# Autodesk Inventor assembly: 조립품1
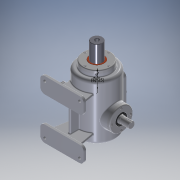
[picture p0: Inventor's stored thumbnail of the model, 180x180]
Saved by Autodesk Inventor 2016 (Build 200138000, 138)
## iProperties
Created: 2018-11
Part Number: 조립품1
Material: 일반
Document SubType Name: Assembly
Designer: user
Mass: 8191.33 g
Surface Area: 4241.85 cm^2
Volume: 1855.51 cm^3
Density: 4.41461 g/cm^3
Author: user
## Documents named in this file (15)
- C:\Users\user\Desktop\381121V1010\조립품1.iam
- C:\Users\user\Desktop\381121V1010\상부커버.ipt
- C:\Users\user\Desktop\381121V1010\슬라이드 커버.ipt
- C:\Users\user\Desktop\381121V1010\슬라이드.ipt
- C:\Users\user\Desktop\381121V1010\오일실.ipt
- 오일실.ipt
- C:\Users\user\Desktop\381121V1010\육각머리볼트 M4.ipt
- C:\Users\user\Desktop\381121V1010\축 커버.ipt
- C:\Users\user\Desktop\381121V1010\편심축.ipt
- C:\Users\user\Desktop\381121V1010\가변스프링.ipt
- C:\Users\user\Desktop\381121V1010\베어링 6205.ipt
- 베어링 6205.ipt
- C:\Users\user\Desktop\381121V1010\본체.ipt
- C:\Users\user\Desktop\381121V1010\볼트 M4x0.7.ipt
- C:\Users\user\Desktop\381121V1010\부시.ipt
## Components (13 placed, 2 different names)
1. 가변스프링:1
2. M4x0.7:1
3. M4x0.7:2
4. M4x0.7:3
5. M4x0.7:4
6. M4x0.7:5
7. M4x0.7:6
8. M4x0.7:7
9. M4x0.7:8
10. M4x0.7:9
11. M4x0.7:10
12. M4x0.7:11
13. M4x0.7:12
